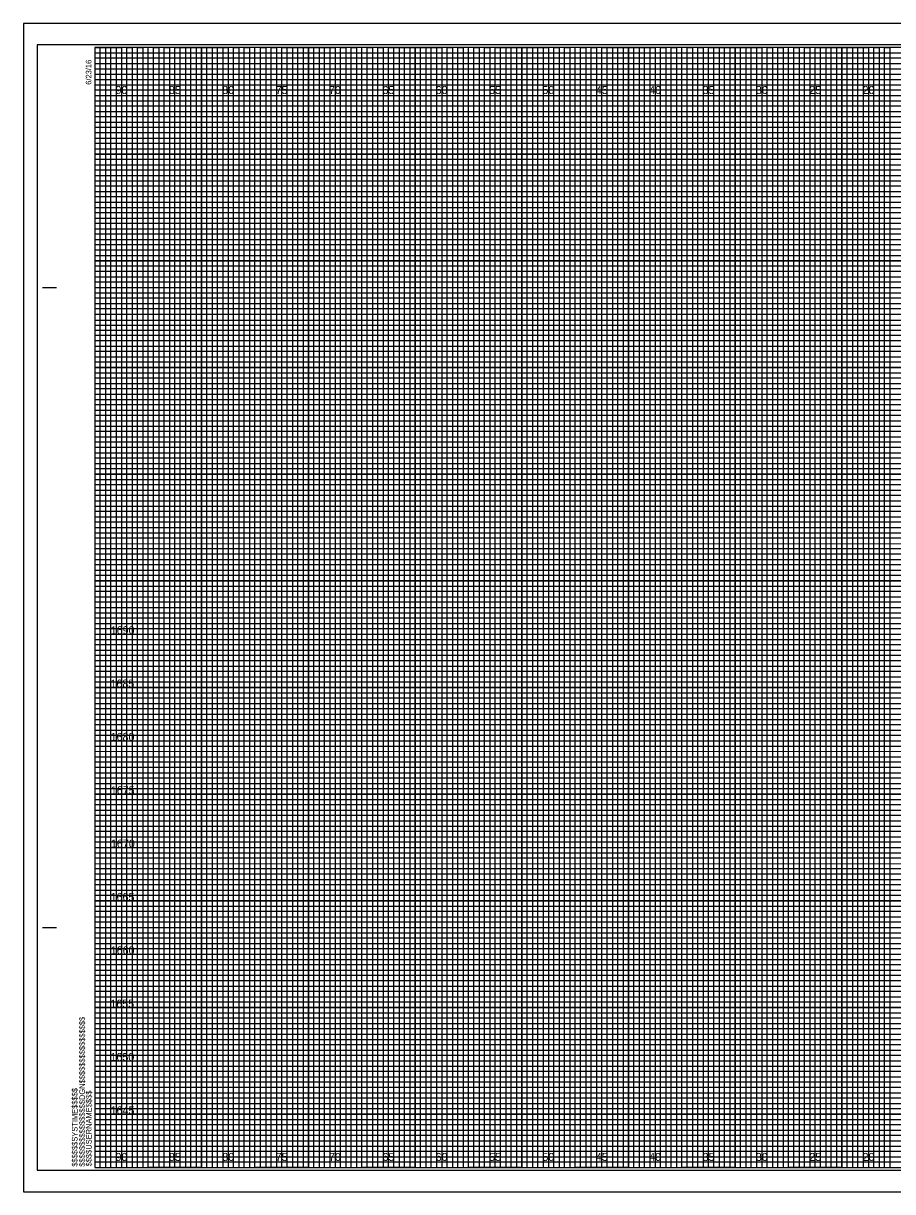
# Model space of a CAD drawing. Extents: x 172 to 723, y -2 to 439.
# Drawn here: x 351.2 to 432.7, y -2.3 to 107.2 of the extents above; entities that cross this region are included whole.
import ezdxf

# ---------------------------------------------------------------- set-up
doc = ezdxf.new("R2010")
doc.units = 0
for name, color, linetype in [('Prop XS Elevation Labels', 7, 'Continuous'), ('Prop XS Offset Labels', 7, 'Continuous'), ('Sheet Cross Section CELL', 7, 'Continuous'), ('Sheet Cross Section Grid Major CELL', 7, 'Continuous'), ('Sheet Cross Section Grid Middle CELL', 7, 'Continuous'), ('Sheet Cross Section Grid Minor 1 CELL', 7, 'Continuous'), ('Sheet Cross Section Grid Minor 2 CELL', 7, 'Continuous'), ('Sheet Cutting Line CELL', 7, 'Continuous'), ('Sheet DOT Grid CELL', 7, 'Continuous'), ('Sheet Plot Border Inside CELL', 7, 'Continuous'), ('Sheet Plot Border Outside CELL', 7, 'Continuous')]:
    doc.layers.add(name, color=color, linetype=linetype)

msp = doc.modelspace()

# ---------------------------------------------------------------- linework, layer by layer
at = {"layer": 'Sheet Cross Section CELL'}
for p, q in [((353.05, 82.46), (354.3, 82.46)), ((353.1, 82.46), (354.35, 82.46)), ((353.05, 22.46), (354.3, 22.46)), ((353.1, 22.46), (354.35, 22.46)), ((357.95, -0.04), (357.95, -0.04)), ((357.95, -0.04), (357.95, -0.04)), ((357.95, -0.04), (357.95, -0.04)), ((357.95, -0.04), (357.95, -0.04)), ((357.95, -0.04), (357.95, -0.04)), ((357.95, -0.04), (357.95, -0.04)), ((357.95, -0.04), (357.95, -0.04))]:
    msp.add_line(p, q, dxfattribs=at)
msp.add_lwpolyline([(517.95, 104.96), (357.95, 104.96), (357.95, -0.04), (517.95, -0.04)], close=True, dxfattribs=at)
at = {"layer": 'Sheet Cross Section Grid Major CELL'}
for p, q in [((362.95, 104.96), (357.95, 104.96)), ((362.95, -0.04), (362.95, 104.96)), ((372.95, 104.96), (367.95, 104.96)), ((367.95, 104.96), (367.95, -0.04)), ((372.95, -0.04), (372.95, 104.96)), ((382.95, 104.96), (377.95, 104.96)), ((377.95, 104.96), (377.95, -0.04)), ((382.95, -0.04), (382.95, 104.96)), ((392.95, 104.96), (387.95, 104.96)), ((387.95, 104.96), (387.95, -0.04)), ((392.95, -0.04), (392.95, 104.96)), ((402.95, 104.96), (397.95, 104.96)), ((397.95, 104.96), (397.95, -0.04)), ((402.95, -0.04), (402.95, 104.96)), ((412.95, 104.96), (407.95, 104.96)), ((407.95, 104.96), (407.95, -0.04)), ((412.95, -0.04), (412.95, 104.96)), ((422.95, 104.96), (417.95, 104.96)), ((417.95, 104.96), (417.95, -0.04)), ((422.95, -0.04), (422.95, 104.96)), ((432.95, 104.96), (427.95, 104.96)), ((427.95, 104.96), (427.95, -0.04)), ((367.95, -0.04), (362.95, -0.04)), ((377.95, -0.04), (372.95, -0.04)), ((387.95, -0.04), (382.95, -0.04)), ((397.95, -0.04), (392.95, -0.04)), ((407.95, -0.04), (402.95, -0.04)), ((417.95, -0.04), (412.95, -0.04)), ((427.95, -0.04), (422.95, -0.04))]:
    msp.add_line(p, q, dxfattribs=at)
for points in [[(357.95, 99.96), (517.95, 99.96), (517.95, 94.96), (357.95, 94.96)], [(357.95, 89.96), (517.95, 89.96), (517.95, 84.96), (357.95, 84.96)], [(357.95, 79.96), (517.95, 79.96), (517.95, 74.96), (357.95, 74.96)], [(357.95, 69.96), (517.95, 69.96), (517.95, 64.96), (357.95, 64.96)], [(357.95, 59.96), (517.95, 59.96), (517.95, 54.96), (357.95, 54.96)], [(357.95, 49.96), (517.95, 49.96), (517.95, 44.96), (357.95, 44.96)], [(357.95, 39.96), (517.95, 39.96), (517.95, 34.96), (357.95, 34.96)], [(357.95, 29.96), (517.95, 29.96), (517.95, 24.96), (357.95, 24.96)], [(357.95, 19.96), (517.95, 19.96), (517.95, 14.96), (357.95, 14.96)], [(357.95, 9.96), (517.95, 9.96), (517.95, 4.96), (357.95, 4.96)]]:
    msp.add_lwpolyline(points, dxfattribs=at)
at = {"layer": 'Sheet Cross Section Grid Middle CELL'}
for points in [[(357.95, 104.96), (360.45, 104.96), (360.45, -0.04), (365.45, -0.04), (365.45, 104.96), (370.45, 104.96), (370.45, -0.04), (375.45, -0.04), (375.45, 104.96), (380.45, 104.96), (380.45, -0.04), (385.45, -0.04), (385.45, 104.96), (390.45, 104.96), (390.45, -0.04), (395.45, -0.04), (395.45, 104.96), (400.45, 104.96), (400.45, -0.04), (405.45, -0.04), (405.45, 104.96), (410.45, 104.96), (410.45, -0.04), (415.45, -0.04), (415.45, 104.96), (420.45, 104.96), (420.45, -0.04), (425.45, -0.04), (425.45, 104.96), (430.45, 104.96), (430.45, -0.04), (435.45, -0.04)], [(357.95, 102.46), (495.45, 102.46)], [(357.95, 92.46), (517.95, 92.46), (517.95, 97.46), (357.95, 97.46)], [(357.95, 82.46), (517.95, 82.46), (517.95, 87.46), (357.95, 87.46)], [(357.95, 72.46), (517.95, 72.46), (517.95, 77.46), (357.95, 77.46)], [(357.95, 62.46), (517.95, 62.46), (517.95, 67.46), (357.95, 67.46)], [(357.95, 52.46), (517.95, 52.46), (517.95, 57.46), (357.95, 57.46)], [(357.95, 42.46), (517.95, 42.46), (517.95, 47.46), (357.95, 47.46)], [(357.95, 32.46), (517.95, 32.46), (517.95, 37.46), (357.95, 37.46)], [(357.95, 22.46), (517.95, 22.46), (517.95, 27.46), (357.95, 27.46)], [(357.95, 12.46), (517.95, 12.46), (517.95, 17.46), (357.95, 17.46)], [(357.95, 2.46), (517.95, 2.46), (517.95, 7.46), (357.95, 7.46)]]:
    msp.add_lwpolyline(points, dxfattribs=at)
at = {"layer": 'Sheet Cross Section Grid Minor 1 CELL'}
for p, q in [((357.95, 104.46), (487.95, 104.46)), ((487.95, 103.95), (357.95, 103.95)), ((357.95, 103.95), (357.95, 103.46)), ((357.95, 103.46), (487.95, 103.46)), ((487.95, 102.91), (357.95, 102.91)), ((357.95, 102.91), (357.95, 101.96)), ((357.95, 101.96), (517.95, 101.96))]:
    msp.add_line(p, q, dxfattribs=at)
for points in [[(357.95, 101.46), (492.95, 101.46), (517.95, 101.46), (517.95, 100.96), (357.95, 100.96)], [(357.95, 100.46), (517.95, 100.46), (517.95, 99.46), (357.95, 99.46)], [(357.95, 98.96), (517.95, 98.96), (517.95, 98.46), (357.95, 98.45)], [(357.95, 97.96), (517.95, 97.96), (517.95, 96.96), (357.95, 96.96)], [(357.95, 96.46), (517.95, 96.46), (517.95, 95.96), (357.95, 95.96)], [(357.95, 95.46), (517.95, 95.46), (517.95, 94.46), (357.95, 94.46)], [(357.95, 93.96), (517.95, 93.96), (517.95, 93.46), (357.95, 93.46)], [(357.95, 92.96), (517.95, 92.96), (517.95, 91.96), (357.95, 91.96)], [(357.95, 91.46), (517.95, 91.46), (517.95, 90.96), (357.95, 90.96)], [(357.95, 90.46), (517.95, 90.46), (517.95, 89.46), (357.95, 89.46)], [(357.95, 88.96), (517.95, 88.96), (517.95, 88.46), (357.95, 88.46)], [(357.95, 87.96), (517.95, 87.96), (517.95, 86.94), (517.95, 86.46), (517.95, 85.96), (357.95, 85.96)], [(357.95, 86.96), (517.95, 86.96), (517.95, 86.46), (357.95, 86.46)], [(357.95, 85.46), (517.95, 85.46), (517.95, 84.46), (357.95, 84.48)], [(357.95, 84.48), (517.95, 84.46), (517.95, 83.96), (357.95, 83.96)], [(357.95, 83.46), (517.95, 83.46), (517.95, 82.96), (357.95, 82.96)], [(357.95, 81.96), (517.95, 81.96), (517.95, 81.46), (357.95, 81.46)], [(357.95, 80.96), (517.95, 80.96), (517.95, 80.46), (357.95, 80.46)], [(357.91, 79.41), (517.95, 79.41), (517.95, 78.9), (357.91, 78.9)], [(357.95, 78.46), (517.95, 78.46), (517.95, 77.96), (357.95, 77.96)], [(357.95, 76.96), (517.95, 76.96), (517.95, 76.46), (357.95, 76.46)], [(357.95, 75.96), (517.95, 75.96), (517.95, 75.46), (357.95, 75.46)], [(357.95, 74.46), (517.95, 74.46), (517.95, 73.96), (357.95, 73.96)], [(357.95, 73.46), (517.95, 73.46), (517.95, 72.96), (357.95, 72.96)], [(357.95, 71.96), (517.95, 71.96), (517.95, 71.46), (357.95, 71.46)], [(357.95, 70.96), (517.95, 70.96), (517.95, 70.46), (357.95, 70.46)], [(357.95, 69.46), (517.95, 69.46), (517.94, 68.95), (357.95, 68.96)], [(357.95, 68.46), (517.95, 68.46), (517.95, 67.96), (357.95, 67.96)], [(357.95, 66.96), (517.95, 66.96), (517.95, 66.46), (357.95, 66.46)], [(357.95, 65.96), (517.95, 65.96), (517.95, 65.46), (357.95, 65.46)], [(357.95, 64.46), (517.95, 64.46), (517.95, 63.96), (357.95, 63.96)], [(357.95, 63.46), (517.95, 63.46), (517.95, 62.96), (357.95, 62.96)], [(357.95, 61.96), (517.95, 61.96), (517.95, 61.46), (357.95, 61.46)], [(357.95, 60.96), (517.95, 60.96), (517.95, 60.46), (357.95, 60.46)], [(357.95, 59.46), (517.95, 59.46), (517.95, 58.96), (357.95, 58.96)], [(357.95, 58.46), (517.98, 58.42), (517.95, 57.96), (357.95, 57.96)], [(357.95, 56.96), (517.95, 56.96), (517.95, 56.46), (357.95, 56.46)], [(357.95, 55.96), (517.95, 55.96), (517.95, 55.46), (357.95, 55.46)], [(357.95, 54.46), (517.95, 54.46), (517.95, 53.96), (357.95, 53.96)], [(357.95, 53.46), (517.95, 53.46), (517.95, 52.96), (357.95, 52.96)], [(357.95, 51.96), (517.95, 51.96), (517.95, 51.46), (357.95, 51.46)], [(357.95, 50.96), (517.95, 50.96), (517.95, 50.46), (357.95, 50.46)], [(357.95, 49.46), (517.95, 49.46), (517.95, 48.96), (357.95, 48.96)], [(357.95, 48.46), (517.95, 48.46), (517.95, 47.96), (357.95, 47.96)], [(357.95, 46.96), (517.95, 46.96), (517.95, 46.46), (357.95, 46.46)], [(357.95, 45.96), (517.95, 45.96), (517.95, 45.46), (357.95, 45.46)], [(357.95, 44.46), (517.95, 44.46), (517.95, 43.96), (357.95, 43.96)], [(357.95, 43.46), (517.95, 43.46), (517.95, 42.96), (357.95, 42.96)], [(357.95, 41.96), (517.95, 41.96), (517.95, 41.46), (357.95, 41.46)], [(357.95, 40.96), (517.95, 40.96), (517.95, 40.46), (357.95, 40.46)], [(357.95, 39.46), (517.95, 39.46), (517.94, 38.95), (357.95, 38.96)], [(357.95, 38.46), (517.95, 38.46), (517.95, 37.96), (357.95, 37.96)], [(357.95, 36.96), (517.95, 36.96), (517.95, 36.46), (357.95, 36.46)], [(357.95, 35.96), (517.95, 35.96), (517.95, 35.46), (357.95, 35.46)], [(357.95, 34.46), (517.95, 34.46), (517.95, 33.96), (357.95, 33.96)], [(357.95, 33.46), (517.95, 33.46), (517.95, 32.96), (357.95, 32.96)], [(357.95, 31.96), (517.95, 31.96), (517.95, 31.46), (357.95, 31.46)], [(357.95, 30.96), (517.95, 30.96), (517.95, 30.46), (357.95, 30.46)], [(357.95, 29.46), (517.95, 29.46), (517.95, 28.96), (357.95, 28.96)], [(357.95, 28.46), (517.98, 28.42), (517.95, 27.96), (357.95, 27.96)], [(357.95, 26.96), (517.95, 26.96), (517.95, 26.46), (357.95, 26.46)], [(357.95, 25.96), (517.95, 25.96), (517.95, 25.46), (357.95, 25.46)], [(357.95, 24.46), (517.95, 24.46), (517.95, 23.96), (357.95, 23.96)], [(357.95, 23.46), (517.95, 23.46), (517.95, 22.96), (357.95, 22.96)], [(357.95, 21.96), (517.95, 21.96), (517.95, 21.46), (357.95, 21.46)], [(357.95, 20.96), (517.95, 20.96), (517.95, 20.46), (357.95, 20.46)], [(357.95, 19.46), (517.95, 19.46), (517.95, 18.96), (357.95, 18.96)], [(357.95, 18.46), (517.95, 18.46), (517.95, 17.96), (357.95, 17.96)], [(357.95, 16.96), (517.95, 16.96), (517.95, 16.46), (357.95, 16.46)], [(357.95, 15.96), (517.95, 15.96), (517.95, 15.46), (357.95, 15.46)], [(357.95, 14.46), (517.95, 14.46), (517.95, 13.96), (357.95, 13.96)], [(357.95, 13.46), (517.95, 13.46), (517.95, 12.96), (357.95, 12.96)], [(357.95, 11.96), (517.95, 11.96), (517.95, 11.46), (357.95, 11.46)], [(357.95, 10.96), (517.95, 10.96), (517.95, 10.46), (357.95, 10.46)], [(357.95, 9.46), (517.95, 9.46), (517.95, 8.96), (357.95, 8.96)], [(357.95, 8.46), (517.95, 8.46), (517.95, 7.96), (357.95, 7.96)], [(357.95, 6.96), (517.95, 6.96), (517.95, 6.46), (357.95, 6.46)], [(357.95, 5.96), (517.95, 5.96), (517.95, 5.46), (357.95, 5.46)], [(357.95, 4.46), (517.95, 4.46), (517.95, 3.96), (357.95, 3.96)], [(357.95, 3.46), (517.95, 3.46), (517.95, 2.96), (357.95, 2.96)], [(357.95, 1.96), (517.95, 1.96), (517.95, 1.46), (357.95, 1.46)], [(357.95, 0.96), (517.95, 0.96), (517.95, 0.46), (357.95, 0.46)]]:
    msp.add_lwpolyline(points, dxfattribs=at)
at = {"layer": 'Sheet Cross Section Grid Minor 2 CELL'}
for points in [[(357.95, -0.04), (358.45, -0.04), (358.45, 104.96), (358.95, 104.96), (358.95, -0.04)], [(358.95, -0.04), (359.45, -0.04), (359.45, 104.96), (359.95, 104.96), (359.95, -0.04)], [(360.45, -0.04), (360.95, -0.04), (360.95, 104.96), (361.45, 104.96), (361.45, -0.04)], [(361.45, -0.04), (361.95, -0.04), (361.95, 104.96), (362.45, 104.96), (362.45, -0.04)], [(362.95, -0.04), (363.45, -0.04), (363.45, 104.96), (363.95, 104.96), (363.95, -0.04)], [(363.95, -0.04), (364.45, -0.04), (364.45, 104.96), (364.95, 104.96), (364.95, -0.04)], [(365.45, -0.04), (365.95, -0.04), (365.95, 104.96), (366.45, 104.96), (366.45, -0.04)], [(366.45, -0.04), (366.95, -0.04), (366.95, 104.96), (367.45, 104.96), (367.45, -0.04)], [(367.95, -0.04), (368.45, -0.04), (368.45, 104.96), (368.95, 104.96), (368.95, -0.04)], [(368.95, -0.04), (369.45, -0.04), (369.45, 104.96), (369.95, 104.96), (369.95, -0.04)], [(370.45, -0.04), (370.95, -0.04), (370.95, 104.96), (371.45, 104.96), (371.45, -0.04)], [(371.45, -0.04), (371.95, -0.04), (371.95, 104.96), (372.45, 104.96), (372.45, -0.04)], [(372.95, -0.04), (373.45, -0.04), (373.45, 104.96), (373.95, 104.96), (373.95, -0.04)], [(373.95, -0.04), (374.45, -0.04), (374.45, 104.96), (374.95, 104.96), (374.95, -0.04)], [(375.45, -0.04), (375.95, -0.04), (375.95, 104.96), (376.45, 104.96), (376.45, -0.04)], [(376.45, -0.04), (376.95, -0.04), (376.95, 104.96), (377.45, 104.96), (377.45, -0.04)], [(377.95, -0.04), (378.45, -0.04), (378.45, 104.96), (378.95, 104.96), (378.95, -0.04)], [(378.95, -0.04), (379.45, -0.04), (379.45, 104.96), (379.95, 104.96), (379.95, -0.04)], [(380.45, -0.04), (380.95, -0.04), (380.95, 104.96), (381.45, 104.96), (381.45, -0.04)], [(381.45, -0.04), (381.95, -0.04), (381.95, 104.96), (382.45, 104.96), (382.45, -0.04)], [(382.95, -0.04), (383.45, -0.04), (383.45, 104.96), (383.95, 104.96), (383.95, -0.04)], [(383.95, -0.04), (384.45, -0.04), (384.45, 104.96), (384.95, 104.96), (384.95, -0.04)], [(385.45, -0.04), (385.95, -0.04), (385.95, 104.96), (386.45, 104.96), (386.45, -0.04)], [(386.45, -0.04), (386.95, -0.04), (386.95, 104.96), (387.45, 104.96), (387.45, -0.04)], [(387.95, -0.04), (388.45, -0.04), (388.45, 104.96), (388.95, 104.96), (388.95, -0.04)], [(388.95, -0.04), (389.45, -0.04), (389.45, 104.96), (389.95, 104.96), (389.95, -0.04)], [(390.45, -0.04), (390.95, -0.04), (390.95, 104.96), (391.45, 104.96), (391.45, -0.04)], [(391.45, -0.04), (391.95, -0.04), (391.95, 104.96), (392.45, 104.96), (392.45, -0.04)], [(392.95, -0.04), (393.45, -0.04), (393.45, 104.96), (393.95, 104.96), (393.95, -0.04)], [(393.95, -0.04), (394.45, -0.04), (394.45, 104.96), (394.95, 104.96), (394.95, -0.04)], [(395.45, -0.04), (395.95, -0.04), (395.95, 104.96), (396.45, 104.96), (396.45, -0.04)], [(396.45, -0.04), (396.95, -0.04), (396.95, 104.96), (397.45, 104.96), (397.45, -0.04)], [(397.95, -0.04), (398.45, -0.04), (398.45, 104.96), (398.95, 104.96), (398.95, -0.04)], [(398.95, -0.04), (399.45, -0.04), (399.45, 104.96), (399.95, 104.96), (399.95, -0.04)], [(400.45, -0.04), (400.95, -0.04), (400.95, 104.96), (401.45, 104.96), (401.45, -0.04)], [(401.45, -0.04), (401.95, -0.04), (401.95, 104.96), (402.45, 104.96), (402.45, -0.04)], [(402.95, -0.04), (403.45, -0.04), (403.45, 104.96), (403.95, 104.96), (403.95, -0.04)], [(403.95, -0.04), (404.45, -0.04), (404.45, 104.96), (404.95, 104.96), (404.95, -0.04)], [(405.45, -0.04), (405.95, -0.04), (405.95, 104.96), (406.45, 104.96), (406.45, -0.04)], [(406.45, -0.04), (406.95, -0.04), (406.95, 104.96), (407.45, 104.96), (407.45, -0.04)], [(407.95, -0.04), (408.45, -0.04), (408.45, 104.96), (408.95, 104.96), (408.95, -0.04)], [(408.95, -0.04), (409.45, -0.04), (409.45, 104.96), (409.95, 104.96), (409.95, -0.04)], [(410.45, -0.04), (410.95, -0.04), (410.95, 104.96), (411.45, 104.96), (411.45, -0.04)], [(411.45, -0.04), (411.95, -0.04), (411.95, 104.96), (412.45, 104.96), (412.45, -0.04)], [(412.95, -0.04), (413.45, -0.04), (413.45, 104.96), (413.95, 104.96), (413.95, -0.04)], [(413.95, -0.04), (414.45, -0.04), (414.45, 104.96), (414.95, 104.96), (414.95, -0.04)], [(415.45, -0.04), (415.95, -0.04), (415.95, 104.96), (416.45, 104.96), (416.45, -0.04)], [(416.45, -0.04), (416.95, -0.04), (416.95, 104.96), (417.45, 104.96), (417.45, -0.04)], [(417.95, -0.04), (418.45, -0.04), (418.45, 104.96), (418.95, 104.96), (418.95, -0.04)], [(418.95, -0.04), (419.45, -0.04), (419.45, 104.96), (419.95, 104.96), (419.95, -0.04)], [(420.45, -0.04), (420.95, -0.04), (420.95, 104.96), (421.45, 104.96), (421.45, -0.04)], [(421.45, -0.04), (421.95, -0.04), (421.95, 104.96), (422.45, 104.96), (422.45, -0.04)], [(422.95, -0.04), (423.45, -0.04), (423.45, 104.96), (423.95, 104.96), (423.95, -0.04)], [(423.95, -0.04), (424.45, -0.04), (424.45, 104.96), (424.95, 104.96), (424.95, -0.04)], [(425.45, -0.04), (425.95, -0.04), (425.95, 104.96), (426.45, 104.96), (426.45, -0.04)], [(426.45, -0.04), (426.95, -0.04), (426.95, 104.96), (427.45, 104.96), (427.45, -0.04)], [(427.95, -0.04), (428.45, -0.04), (428.45, 104.96), (428.95, 104.96), (428.95, -0.04)], [(428.95, -0.04), (429.45, -0.04), (429.45, 104.96), (429.95, 104.96), (429.95, -0.04)], [(430.45, -0.04), (430.95, -0.04), (430.95, 104.96), (431.45, 104.96), (431.45, -0.04)], [(431.45, -0.04), (431.95, -0.04), (431.95, 104.96), (432.45, 104.96), (432.45, -0.04)]]:
    msp.add_lwpolyline(points, dxfattribs=at)
at = {"layer": 'Sheet Cutting Line CELL'}
for p, q in [((519.6, 107.21), (351.25, 107.21)), ((351.25, 107.21), (351.25, -2.29)), ((351.25, -2.29), (519.6, -2.29))]:
    msp.add_line(p, q, dxfattribs=at)
at = {"layer": 'Sheet DOT Grid CELL'}
for p, q in [((362.95, -0.04), (362.95, 104.96)), ((367.95, -0.04), (367.95, 104.96)), ((372.95, -0.04), (372.95, 104.96)), ((377.95, -0.04), (377.95, 104.96)), ((382.95, -0.04), (382.95, 104.96)), ((387.95, -0.04), (387.95, 104.96)), ((392.95, -0.04), (392.95, 104.96)), ((397.95, -0.04), (397.95, 104.96)), ((402.95, -0.04), (402.95, 104.96)), ((407.95, -0.04), (407.95, 104.96)), ((412.95, -0.04), (412.95, 104.96)), ((417.95, -0.04), (417.95, 104.96)), ((422.95, -0.04), (422.95, 104.96)), ((427.95, -0.04), (427.95, 104.96)), ((357.95, 99.96), (517.95, 99.96)), ((357.95, 94.96), (517.95, 94.96)), ((357.95, 89.96), (517.95, 89.96)), ((357.95, 84.96), (517.95, 84.96)), ((357.95, 79.96), (517.95, 79.96)), ((357.95, 74.96), (517.95, 74.96)), ((357.95, 69.96), (517.95, 69.96)), ((357.95, 64.96), (517.95, 64.96)), ((357.95, 59.96), (517.95, 59.96)), ((357.95, 54.96), (517.95, 54.96)), ((357.95, 49.96), (517.95, 49.96)), ((357.95, 44.96), (517.95, 44.96)), ((357.95, 39.96), (517.95, 39.96)), ((357.95, 34.96), (517.95, 34.96)), ((357.95, 29.96), (517.95, 29.96)), ((357.95, 24.96), (517.95, 24.96)), ((357.95, 19.96), (517.95, 19.96)), ((357.95, 14.96), (517.95, 14.96)), ((357.95, 9.96), (517.95, 9.96)), ((357.95, 4.96), (517.95, 4.96))]:
    msp.add_line(p, q, dxfattribs=at)
at = {"layer": 'Sheet Plot Border Inside CELL'}
msp.add_lwpolyline([(352.55, -0.29), (519.15, -0.29), (519.15, 105.21), (352.55, 105.21)], close=True, dxfattribs=at)
at = {"layer": 'Sheet Plot Border Outside CELL'}
msp.add_lwpolyline([(351.25, -2.29), (519.6, -2.29), (519.6, 107.21), (351.25, 107.21)], close=True, dxfattribs=at)

# ---------------------------------------------------------------- texts
at = {"layer": 'Prop XS Elevation Labels'}
for s, p in [('1690', (359.43, 49.96)), ('1685', (359.41, 44.96)), ('1680', (359.42, 39.96)), ('1675', (359.44, 34.96)), ('1670', (359.45, 29.96)), ('1665', (359.42, 24.96)), ('1660', (359.43, 19.96)), ('1655', (359.4, 14.96)), ('1650', (359.41, 9.96)), ('1645', (359.42, 4.96))]:
    msp.add_text(s, height=0.75, dxfattribs=at).set_placement(p)
at = {"layer": 'Prop XS Offset Labels'}
for s, p in [('90', (359.88, 100.59)), ('85', (364.89, 100.59)), ('80', (369.88, 100.59)), ('75', (374.89, 100.59)), ('70', (379.88, 100.59)), ('65', (384.89, 100.59)), ('60', (389.88, 100.59)), ('55', (394.89, 100.59)), ('50', (399.88, 100.59)), ('45', (404.89, 100.59)), ('40', (409.88, 100.59)), ('35', (414.89, 100.59)), ('30', (419.88, 100.59)), ('25', (424.89, 100.59)), ('20', (429.88, 100.59)), ('90', (359.88, 0.59)), ('85', (364.89, 0.59)), ('80', (369.88, 0.59)), ('75', (374.89, 0.59)), ('70', (379.88, 0.59)), ('65', (384.89, 0.59)), ('60', (389.88, 0.59)), ('55', (394.89, 0.59)), ('50', (399.88, 0.59)), ('45', (404.89, 0.59)), ('40', (409.88, 0.59)), ('35', (414.89, 0.59)), ('30', (419.88, 0.59)), ('25', (424.89, 0.59)), ('20', (429.88, 0.59))]:
    msp.add_text(s, height=0.75, dxfattribs=at).set_placement(p)
at = {"layer": 'Sheet Cross Section CELL'}
for s, p in [('6/23/16', (357.62, 101.46)), ('$$$$$$$$$$$$$$$$DGN$$$$$$$$$$$$$$$$', (357.01, 0.05)), ('$$$$$$SYSTIME$$$$$', (356.32, 0.05)), ('$$$$USERNAME$$$$', (357.64, 0.08))]:
    msp.add_text(s, height=0.525, rotation=90, dxfattribs=at).set_placement(p)

doc.saveas('drawing.dxf')
